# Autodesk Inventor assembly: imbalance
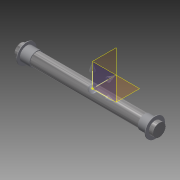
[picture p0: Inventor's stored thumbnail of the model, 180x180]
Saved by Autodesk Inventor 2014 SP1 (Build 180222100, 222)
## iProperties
Created: 2014-04
Part Number: imbalance
Document SubType Name: Assembly
Designer: BobvH
Author: BobvH
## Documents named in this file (3)
- C:\Users\bobvh\Documents\Inventor\as movement\imbalance.iam
- C:\Users\bobvh\Documents\Inventor\as movement\sleave bearing.ipt
- C:\Users\bobvh\Documents\Inventor\as movement\center of gravity.ipt
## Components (3 placed, 2 different names)
1. sleave bearing:1 — Mate:1
2. sleave bearing:2 — Mate:2, Mate:3
3. center of gravity:1 — Mate:1, Mate:2, Mate:3, Angle:1
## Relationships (4: Mate 3, Angle 1)
- Mate:1: sleave bearing:1 ↔ center of gravity:1
- Mate:2: sleave bearing:2 ↔ center of gravity:1
- Mate:3: sleave bearing:2 ↔ center of gravity:1
- Angle:1: center of gravity:1
